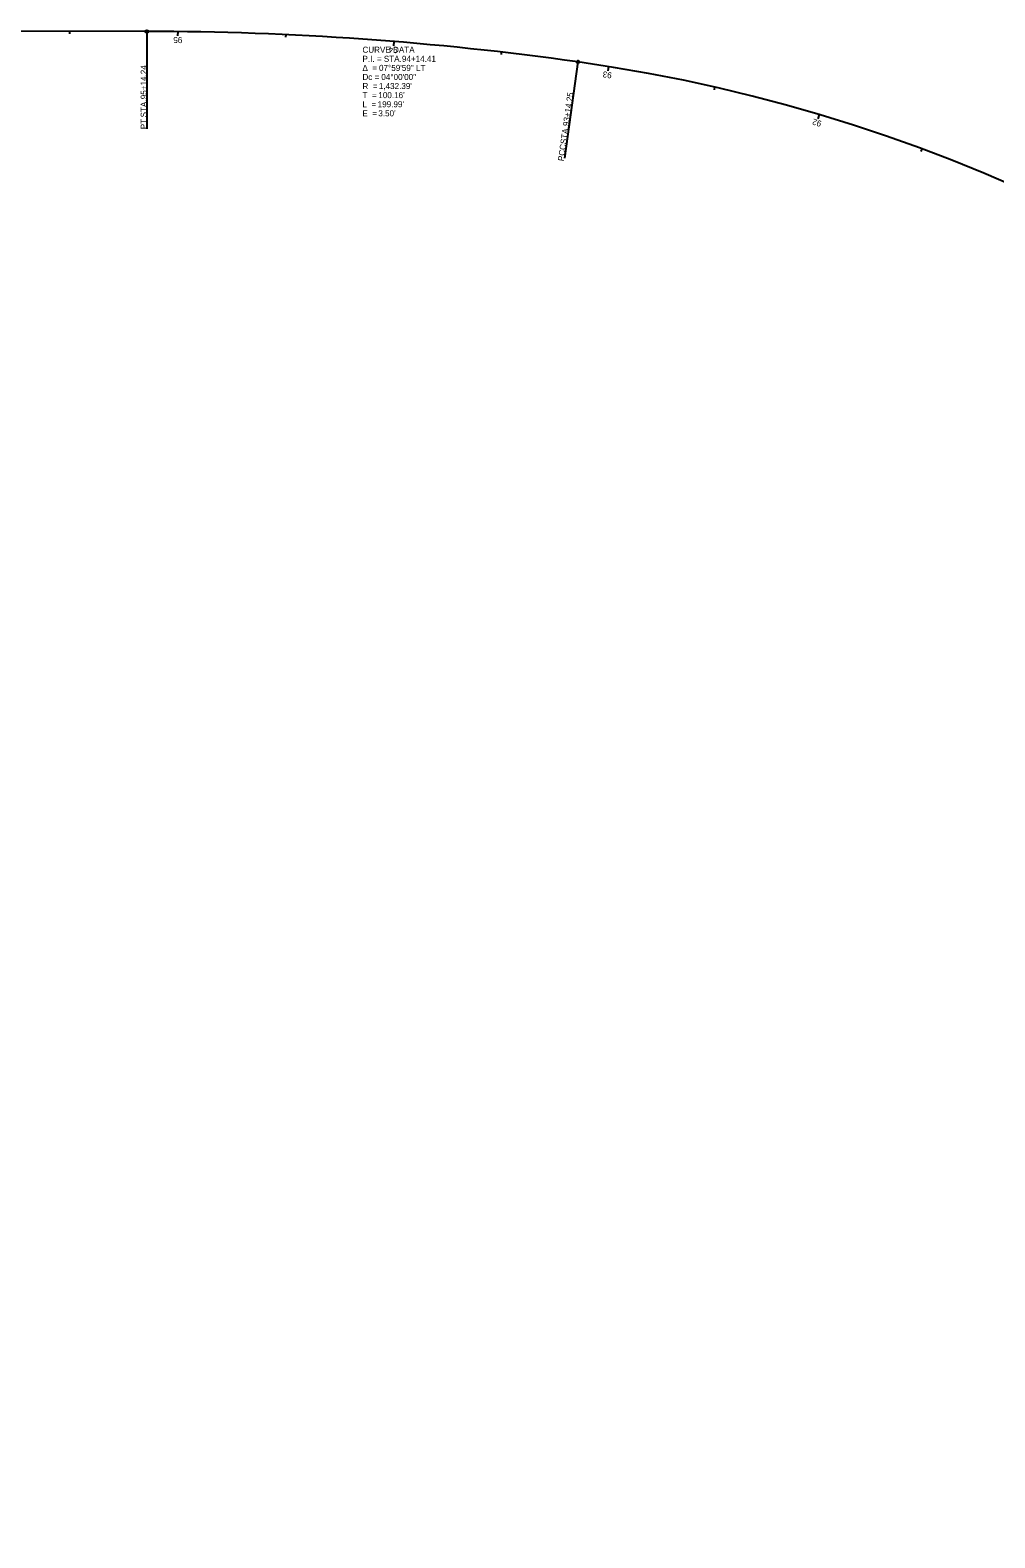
# Model space of a CAD drawing. Extents: x 2200877 to 2202699, y 632416 to 635901.
# Drawn here: x 2201786 to 2202232, y 635100 to 635797 of the extents above; entities that cross this region are included whole.
import ezdxf

# ---------------------------------------------------------------- set-up
doc = ezdxf.new("R2010")
doc.units = 0
for name, color, linetype in [('_CIVIL_CONSTRUCTION', 7, 'Continuous'), ('RW_X_CL', 7, 'Continuous'), ('RW_X_CL_100_Cardinal_Points', 7, 'Continuous'), ('SH_Data', 7, 'Continuous')]:
    doc.layers.add(name, color=color, linetype=linetype)

msp = doc.modelspace()

# ---------------------------------------------------------------- linework, layer by layer
at = {"layer": 'RW_X_CL'}
for p, q in [((2201839.67, 635796.38), (2201839.63, 635751.38)), ((2202039, 635782.28), (2202032.7, 635737.72))]:
    msp.add_line(p, q, dxfattribs=at)
for centre in [(2201839.67, 635796.38), (2202039, 635782.28)]:
    msp.add_circle(centre, 0.6, dxfattribs=at)
at = {"layer": 'RW_X_CL_100_Cardinal_Points'}
for p, q in [((2201803.91, 635796.41), (2201803.91, 635795.21)), ((2201853.91, 635796.3), (2201853.89, 635794.3)), ((2201903.89, 635794.89), (2201903.84, 635793.69)), ((2201953.79, 635791.73), (2201953.63, 635789.74)), ((2202003.55, 635786.84), (2202003.41, 635785.65)), ((2202053.09, 635780.15), (2202052.78, 635778.18)), ((2202102.17, 635770.62), (2202101.9, 635769.45)), ((2202150.51, 635757.9), (2202149.94, 635755.99)), ((2202197.93, 635742.05), (2202197.51, 635740.92))]:
    msp.add_line(p, q, dxfattribs=at)
at = {"layer": 'SH_Data'}
msp.add_line((2201839.67, 635796.38), (2201448.67, 635796.7), dxfattribs=at)
msp.add_line((2201839.67, 635796.38), (2201448.67, 635796.7), dxfattribs=at)
for centre, radius, start, end in [((2201838.51, 634363.99), 1432.39, 81.9537, 89.95343), ((2201838.51, 634363.99), 1432.39, 81.9537, 89.95343), ((2201932.07, 635025.86), 763.94, 5.2962, 81.9537), ((2201932.07, 635025.86), 763.94, 5.2962, 81.9537)]:
    msp.add_arc(centre, radius, start, end, dxfattribs=at)

# ---------------------------------------------------------------- texts
at = {"layer": '_CIVIL_CONSTRUCTION'}
for s, p in [('CURVE DATA', (2201939.34, 635786.53)), ('Δ  = ', (2201939.34, 635778.13)), ('P.I. = STA. ', (2201939.34, 635782.33)), ('07°59\'59" LT', (2201947.01, 635778.13)), ('94+14.41', (2201957.6, 635782.33)), ('Dc = ', (2201939.34, 635773.93)), ('04°00\'00"', (2201948.08, 635773.93)), ('T  = ', (2201939.34, 635765.53)), ('R  = ', (2201939.34, 635769.73)), ("100.16'", (2201946.68, 635765.53)), ("1,432.39'", (2201946.92, 635769.73)), ('L  = ', (2201939.34, 635761.33)), ('E  = ', (2201939.34, 635757.13)), ("199.99'", (2201946.38, 635761.33)), ("3.50'", (2201946.68, 635757.13))]:
    msp.add_text(s, height=2.8, dxfattribs=at).set_placement(p)
at = {"layer": 'RW_X_CL'}
for s, rotation, p in [('95+14.24', 89.95343, (2201839.6, 635765.03)), ('93+14.25', 81.9537, (2202034.74, 635752.44)), (' STA. ', 89.95343, (2201839.6, 635755.58)), ('PT', 89.95343, (2201839.59, 635751.17)), (' STA. ', 81.9537, (2202033.42, 635743.08)), ('PCC', 81.9537, (2202032.46, 635736.26))]:
    msp.add_text(s, height=2.8, rotation=rotation, dxfattribs=at).set_placement(p)
at = {"layer": 'RW_X_CL_100_Cardinal_Points'}
for s, rotation, p in [('95', 179.38368, (2201856.07, 635793.77)), ('94', 175.38368, (2201955.74, 635789.07)), ('93', 170.88491, (2202054.83, 635777.34)), ('92', 163.38491, (2202151.87, 635754.89))]:
    msp.add_text(s, height=2.8, rotation=rotation, dxfattribs=at).set_placement(p)

doc.saveas('drawing.dxf')
